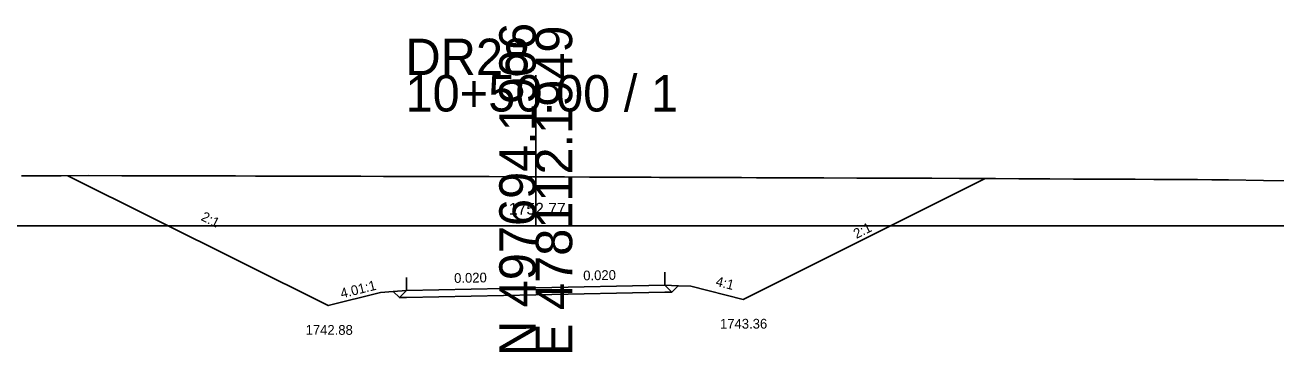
# Model space of a CAD drawing. Extents: x -26 to 303, y -10 to 3689.
# Drawn here: x 110.8 to 206.8, y 990.3 to 1015.4 of the extents above; entities that cross this region are included whole.
import ezdxf

# ---------------------------------------------------------------- set-up
doc = ezdxf.new("R2010")
doc.units = 0
for name, color, linetype in [('Exist Cross Section Cell', 7, 'Continuous'), ('Exist XS Center Line Elevation Label', 7, 'Continuous'), ('Exist XS Ground Line', 7, 'Continuous'), ('Prop XS Ditch Slope Text', 7, 'Continuous'), ('Prop XS Ditch Standard Text', 7, 'Continuous'), ('Prop XS Dump Level', 7, 'Continuous'), ('Prop XS Earthwork Shape', 7, 'Continuous'), ('Prop XS EOT Tick Mark', 7, 'Continuous'), ('Prop XS Finish Grade', 7, 'Continuous'), ('Prop XS Finish Grade Earthwork', 7, 'Continuous'), ('Prop XS Finish Grade Pavement', 7, 'Continuous'), ('Prop XS Hydro Typical Ditch Data', 7, 'Continuous'), ('Prop XS Pvmt Edge Slope', 7, 'Continuous'), ('Prop XS SE Text', 7, 'Continuous'), ('Prop XS Shoulder Borrow Shape', 7, 'Continuous'), ('Prop XS Side Slope Text', 7, 'Continuous'), ('Prop XS Subgrade Earthwork', 7, 'Continuous')]:
    doc.layers.add(name, color=color, linetype=linetype)

msp = doc.modelspace()

# ---------------------------------------------------------------- linework, layer by layer
at = {"layer": 'Exist Cross Section Cell'}
for p, q in [((150, 1000), (150, 1011.592)), ((0, 1000), (150, 1000)), ((150, 1000), (300, 1000))]:
    msp.add_line(p, q, dxfattribs=at)
at = {"layer": 'Exist XS Ground Line'}
msp.add_lwpolyline([(110.539, 1003.857), (112.37, 1003.858), (113.109, 1003.859), (113.576, 1003.86), (115.699, 1003.864), (118.239, 1003.854), (119.011, 1003.853), (120.8, 1003.847), (121.938, 1003.846), (123.375, 1003.845), (124.036, 1003.844), (126.118, 1003.839), (126.944, 1003.838), (128.493, 1003.835), (130.298, 1003.831), (131.049, 1003.83), (132.395, 1003.827), (133.619, 1003.822), (134.483, 1003.82), (136.185, 1003.815), (136.58, 1003.813), (138.326, 1003.807), (138.757, 1003.806), (140.763, 1003.802), (141.317, 1003.8), (142.194, 1003.797), (143.881, 1003.794), (145.518, 1003.792), (146.434, 1003.792), (149.005, 1003.778), (149.466, 1003.776), (150, 1003.773), (151.568, 1003.763), (152.202, 1003.761), (154.137, 1003.751), (155.539, 1003.746), (156.698, 1003.741), (158.865, 1003.736), (159.508, 1003.733), (160.651, 1003.731), (161.82, 1003.727), (163.705, 1003.719), (164.379, 1003.716), (165.805, 1003.71), (166.949, 1003.708), (167.892, 1003.705), (169.522, 1003.7), (172.107, 1003.688), (174.649, 1003.679), (175.432, 1003.677), (177.21, 1003.675), (178.784, 1003.669), (179.778, 1003.665), (180.396, 1003.662), (182.514, 1003.651), (183.277, 1003.647), (184.722, 1003.641), (185.284, 1003.632), (187.078, 1003.619), (188.377, 1003.613), (189.465, 1003.606), (191.287, 1003.594), (191.884, 1003.592), (192.585, 1003.591), (194.337, 1003.592), (194.984, 1003.59), (196, 1003.583), (197.434, 1003.574), (198.386, 1003.568), (198.85, 1003.566), (200.799, 1003.561), (201.902, 1003.54), (203.179, 1003.529), (205.862, 1003.478), (207.846, 1003.47)], dxfattribs=at)
at = {"layer": 'Prop XS Dump Level'}
for p, q in [((140.09, 995.04), (150, 995.238)), ((150, 995.238), (159.911, 995.436))]:
    msp.add_line(p, q, dxfattribs=at)
at = {"layer": 'Prop XS Earthwork Shape'}
for points in [[(165.805, 1003.71), (166.949, 1003.708), (167.892, 1003.705), (169.522, 1003.7), (172.107, 1003.688), (174.649, 1003.679), (175.432, 1003.677), (177.21, 1003.675), (178.784, 1003.669), (179.778, 1003.665), (180.396, 1003.662), (182.514, 1003.651), (183.277, 1003.647), (184.493, 1003.642), (165.914, 994.356), (161.912, 995.356), (160.933, 995.396), (160.442, 994.905), (159.911, 994.895), (150, 994.697), (140.09, 994.498), (139.536, 994.487), (139.064, 994.958), (138.086, 994.88), (134.079, 993.88), (114.083, 1003.861), (115.699, 1003.864), (118.239, 1003.854), (119.011, 1003.853), (120.8, 1003.847), (121.938, 1003.846), (123.375, 1003.845), (124.036, 1003.844), (126.118, 1003.839), (126.944, 1003.838), (128.493, 1003.835), (130.298, 1003.831), (131.049, 1003.83), (132.395, 1003.827), (133.619, 1003.822), (134.483, 1003.82), (136.185, 1003.815), (136.58, 1003.813), (138.326, 1003.807), (138.757, 1003.806), (140.763, 1003.802), (141.317, 1003.8), (142.194, 1003.797), (143.881, 1003.794), (145.518, 1003.792), (146.434, 1003.792), (149.005, 1003.778), (149.466, 1003.776), (150, 1003.773), (151.568, 1003.763), (152.202, 1003.761), (154.137, 1003.751), (155.539, 1003.746), (156.698, 1003.741), (158.865, 1003.736), (159.508, 1003.733), (160.651, 1003.731), (161.82, 1003.727), (163.705, 1003.719), (164.379, 1003.716)], [(175.432, 1003.677), (177.21, 1003.675), (178.784, 1003.669), (179.778, 1003.665), (180.396, 1003.662), (182.514, 1003.651), (183.277, 1003.647), (184.493, 1003.642), (165.914, 994.356), (161.912, 995.356), (160.933, 995.396), (160.442, 994.905), (159.911, 994.895), (150, 994.697), (140.09, 994.498), (139.536, 994.487), (139.064, 994.958), (138.086, 994.88), (134.079, 993.88), (114.083, 1003.861), (115.699, 1003.864), (118.239, 1003.854), (119.011, 1003.853), (120.8, 1003.847), (121.938, 1003.846), (123.375, 1003.845), (124.036, 1003.844), (126.118, 1003.839), (126.944, 1003.838), (128.493, 1003.835), (130.298, 1003.831), (131.049, 1003.83), (132.395, 1003.827), (133.619, 1003.822), (134.483, 1003.82), (136.185, 1003.815), (136.58, 1003.813), (138.326, 1003.807), (138.757, 1003.806), (140.763, 1003.802), (141.317, 1003.8), (142.194, 1003.797), (143.881, 1003.794), (145.518, 1003.792), (146.434, 1003.792), (149.005, 1003.778), (149.466, 1003.776), (150, 1003.773), (151.568, 1003.763), (152.202, 1003.761), (154.137, 1003.751), (155.539, 1003.746), (156.698, 1003.741), (158.865, 1003.736), (159.508, 1003.733), (160.651, 1003.731), (161.82, 1003.727), (163.705, 1003.719), (164.379, 1003.716), (165.805, 1003.71), (166.949, 1003.708), (167.892, 1003.705), (169.522, 1003.7), (172.107, 1003.688), (174.649, 1003.679)]]:
    msp.add_lwpolyline(points, close=True, dxfattribs=at)
at = {"layer": 'Prop XS EOT Tick Mark'}
for p, q in [((140.09, 995.04), (140.09, 996.04)), ((159.911, 995.436), (159.911, 996.436))]:
    msp.add_line(p, q, dxfattribs=at)
at = {"layer": 'Prop XS Finish Grade'}
for p, q in [((140.09, 995.04), (139.064, 994.958)), ((159.911, 995.436), (160.933, 995.396))]:
    msp.add_line(p, q, dxfattribs=at)
at = {"layer": 'Prop XS Finish Grade Earthwork'}
for p, q in [((134.079, 993.88), (114.083, 1003.861)), ((165.914, 994.356), (184.493, 1003.642)), ((138.086, 994.88), (134.079, 993.88)), ((139.064, 994.958), (138.086, 994.88)), ((160.933, 995.396), (161.912, 995.356)), ((161.912, 995.356), (165.914, 994.356))]:
    msp.add_line(p, q, dxfattribs=at)
at = {"layer": 'Prop XS Finish Grade Pavement'}
for p, q in [((140.09, 995.04), (150, 995.238)), ((150, 995.238), (159.911, 995.436))]:
    msp.add_line(p, q, dxfattribs=at)
at = {"layer": 'Prop XS Hydro Typical Ditch Data'}
for p, q in [((134.079, 993.88), (114.083, 1003.861)), ((138.086, 994.88), (134.079, 993.88))]:
    msp.add_line(p, q, dxfattribs=at)
at = {"layer": 'Prop XS Pvmt Edge Slope'}
for p, q in [((140.09, 995.04), (139.536, 994.487)), ((159.911, 995.436), (160.442, 994.905))]:
    msp.add_line(p, q, dxfattribs=at)
at = {"layer": 'Prop XS Shoulder Borrow Shape'}
for points in [[(140.09, 995.04), (139.064, 994.958), (139.536, 994.487)], [(159.911, 995.436), (160.933, 995.396), (160.442, 994.905)]]:
    msp.add_lwpolyline(points, close=True, dxfattribs=at)
at = {"layer": 'Prop XS Subgrade Earthwork'}
for p, q in [((139.536, 994.487), (139.064, 994.958)), ((159.911, 994.895), (150, 994.697)), ((159.911, 994.895), (160.442, 994.905)), ((160.442, 994.905), (160.933, 995.396)), ((140.09, 994.498), (139.536, 994.487)), ((150, 994.697), (140.09, 994.499))]:
    msp.add_line(p, q, dxfattribs=at)

# ---------------------------------------------------------------- texts
at = {"layer": 'Exist Cross Section Cell'}
for s, p in [('N 497694.1906', (150, 990)), ('E 478112.1949', (152.8, 990))]:
    msp.add_text(s, height=2.8, rotation=90, dxfattribs=at).set_placement(p)
for s, p in [('DR28', (140, 1011.592)), ('10+50.00 / 1', (140, 1008.792))]:
    msp.add_text(s, height=2.8, dxfattribs=at).set_placement(p)
at = {"layer": 'Exist XS Center Line Elevation Label'}
msp.add_text('1752.77', height=0.9, dxfattribs=at).set_placement((147.945, 1000.873))
at = {"layer": 'Prop XS Ditch Slope Text'}
for s, rotation, p in [('4.01:1', 14.01315, (135.107, 994.429)), ('4:1', 345.97031, (163.761, 995.407))]:
    msp.add_text(s, height=0.75, rotation=rotation, dxfattribs=at).set_placement(p)
at = {"layer": 'Prop XS Ditch Standard Text'}
for s, p in [('1743.36', (164.143, 992.106)), ('1742.88', (132.334, 991.63))]:
    msp.add_text(s, height=0.75, dxfattribs=at).set_placement(p)
at = {"layer": 'Prop XS Dump Level'}
for p in [(138.086, 994.84), (161.912, 995.316)]:
    msp.add_text('Case1', height=0.04, dxfattribs=at).set_placement(p)
at = {"layer": 'Prop XS SE Text'}
for p in [(143.741, 995.613), (153.652, 995.811)]:
    msp.add_text('0.020', height=0.75, rotation=1.14576, dxfattribs=at).set_placement(p)
at = {"layer": 'Prop XS Side Slope Text'}
for rotation, p in [(333.47422, (124.244, 1000.466)), (26.55391, (174.617, 999.003))]:
    msp.add_text('2:1', height=0.75, rotation=rotation, dxfattribs=at).set_placement(p)

doc.saveas('drawing.dxf')
